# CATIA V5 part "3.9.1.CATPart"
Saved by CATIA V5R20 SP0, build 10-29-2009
Part number: 3.9.1
Material "Silver": density 10491 kg/m3, Young's modulus 7.6e+10 Pa, Poisson ratio 0.37, thermal expansion 1.89e-05 1/K
Bounding box of the stored display mesh (mm): x -59.83 to 69.752, y -28.986 to 28.986, z -10 to 25.562
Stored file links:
  G:\作品\课程作业\3.9.1.CATPart
  D:\ShellExt\wode\win_b64\startup\materials\Catalog.CATMaterial
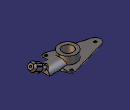
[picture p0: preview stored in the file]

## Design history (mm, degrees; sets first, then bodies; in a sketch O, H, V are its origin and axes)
Body1 (main body), material "Silver"
  Sketch1 on xy-plane, origin (0, 0, 0), H (1, 0, 0), V (0, 1, 0)
    circle A1 centre (-50, 0) radius 2.5
    point P1 (-50, 0)
    line L1 (22, 23.0864) -> (22, -23.0864)
    arc A2 centre (-50, 0) radius 10 from (-52.7564, 9.6126) to (-52.7564, -9.6126) ccw
    line L2 (-52.7564, 9.6126) -> (14.3462, 28.854)
    point P2 (-52.7564, 9.6126)
    arc A3 centre (16, 23.0864) radius 6 from (14.3462, 28.854) to (22, 23.0864) cw
    point P3 (14.3462, 28.854)
    point P4 (22, 23.0864)
    circle A4 centre (16, 23.0864) radius 2.5
    point P6 (14.3462, -28.854)
    point P7 (-52.7564, -9.6126)
    line L3 (-52.7564, -9.6126) -> (14.3462, -28.854)
    point P8 (22, -23.0864)
    arc A5 centre (16, -23.0864) radius 6 from (14.3462, -28.854) to (22, -23.0864) ccw
    circle A6 centre (16, -23.0864) radius 2.5
    radius A1 = 2.5
    distance L1 V = 22
    distance P1 L1 = 72
    angle L2 H = 16
    radius A2 = 10
    radius A4 = 2.5
    coincidence: P1 H
    vertical: L1 V
    tangency: A2 L2, A3 L2, A3 L1
    symmetry: P3 P6 H, P2 P7 H, L2 L3 H, P4 P8 H, A3 A5 H, A4 A6 H
  Pad1: profile Sketch1, direction (0, 0, 1), length 1.5
  TritangentFillet1: Face1 end face of Pad1, RemoveFace face of Pad1 from Sketch1.L1, Face2 start face of Pad1
  Sketch2 on xy-plane, origin (0, 0, 0), H (1, 0, 0), V (0, 1, 0)
    circle A1 centre (0, 0) radius 16
  Pad2: profile Sketch2, direction (0, 0, 1), length 15, opposite side length 10
  Sketch3 on yz-plane, origin (0, 0, 0), H (0, 1, 0), V (0, 0, 1)
    arc A1 centre (0, 0) radius 11 from (11, 0) to (-11, 0) ccw
    line L1 (-11, 0) -> (11, 0)
    radius A1 = 11
    horizontal: L1 H
  Pad3: profile Sketch3, direction (1, 0, 0), length 44
  Sketch4 on zx-plane, origin (0, 0, 0), H (0, 0, 1), V (1, 0, 0)
    line L1 (-0.0766, 44.0153) -> (7.4985, 44.0153)
    line L2 (7.4985, 44.0153) -> (10.9676, 38.0066)
    horizontal: L1 H
  Pocket1: profile Sketch4, direction (0, -1, 0), length 20, mirrored extent
  Sketch5 on zx-plane, origin (0, 0, 0), H (0, 0, 1), V (1, 0, 0)
    line L1 (7.0343, 42.6622) -> (21.2318, 67.2531)
    reference projected line E1 (0, 21.25) -> (0, 44) from edge [face of Pad3 from Sketch3.A1 | face of Pad3]
    line L2 (21.2318, 67.2531) -> (25.562, 64.7531)
    reference projected point E2 (7.5074, 44) from vertex [end face of Pad3 | face of Pocket1 | face of Pad3 from Sketch3.A1]
    line L3 (25.562, 64.7531) -> (25.562, 59.7399)
    line L4 (25.562, 59.7399) -> (19.562, 49.3476)
    line L5 (19.562, 49.3476) -> (15.1401, 48.1628)
    line L6 (15.1401, 48.1628) -> (8.7734, 37.1354)
    line L7 (8.7734, 37.1354) -> (5.0759, 39.2702)
    line L8 (5.0759, 39.2702) -> (7.0343, 42.6622)
    angle E1 L1 = 30
    distance E2 L2 = 27
    angle L2 L1 = 90
    length L2 = 5
    angle L3 L1 = 30
    length L4 = 12
    angle L5 L1 = 45
    parallelism: L4 L1, L6 L4, L7 L2, L8 L1
  Shaft1: profile Sketch5, axis Sketch5.L1, angle 360
  Sketch6 on face of Shaft1 from Sketch5.L2, origin (67.2531, 0, 21.2318), H (0.5, 0, -0.866), V (0, -1, 0)
    line L1 (-8.066, 1.4764) -> (-6.8317, 0)
    line L2 (-6.8317, 0) -> (-8.1145, -1.5232)
    line L3 (-8.066, 1.4764) -> (-8.1145, -1.5232)
    angle L1 L2 = 100
    length L3 = 3
  Pocket2: profile Sketch6, direction (-0.866, 0, -0.5), length 22
  CircPattern1: of Pocket2, instances 6, angular step 60, axis from face of Shaft1 from Sketch5.L2
  Sketch7 on zx-plane, origin (0, 0, 0), H (0, 0, 1), V (1, 0, 0)
    line L1 (5, 36.1535) -> (5, 0)
    point P1 (5, 0)
    reference projected line E1 (0, 21.25) -> (0, 44) from edge [face of Pad3 from Sketch3.A1 | face of Pad3]
    line L2 (23.8111, 71.4147) -> (6.3397, 41.1535)
    reference projected line E2 (0, 21.25) -> (0, 44) from edge [face of Pad3 from Sketch3.A1 | face of Pad3]
    arc A1 centre (15, 36.1535) radius 10 from (5, 36.1535) to (6.3397, 41.1535) cw
    distance L1 E1 = 5
    angle L2 E2 = 30
    coincidence: P1 H
    vertical: L1 V
    tangency: A1 L1, A1 L2
  Sketch8 on yz-plane, origin (0, 0, 0), H (0, 1, 0), V (0, 0, 1)
    circle A1 centre (0, 5) radius 2
    point P1 (0, 5)
    distance P1 H = 5
    coincidence: P1 V
  Slot1: profile Sketch8, centre curve Sketch7
  Sketch9 on end face of Pad2, origin (0, 0, 15), H (1, 0, 0), V (0, 1, 0)
    point P1 (0, 0)
  Hole1: placed by Sketch9, at (0, 0, 15) direction (0, 0, -1), diameter 20, through (limit type 3)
